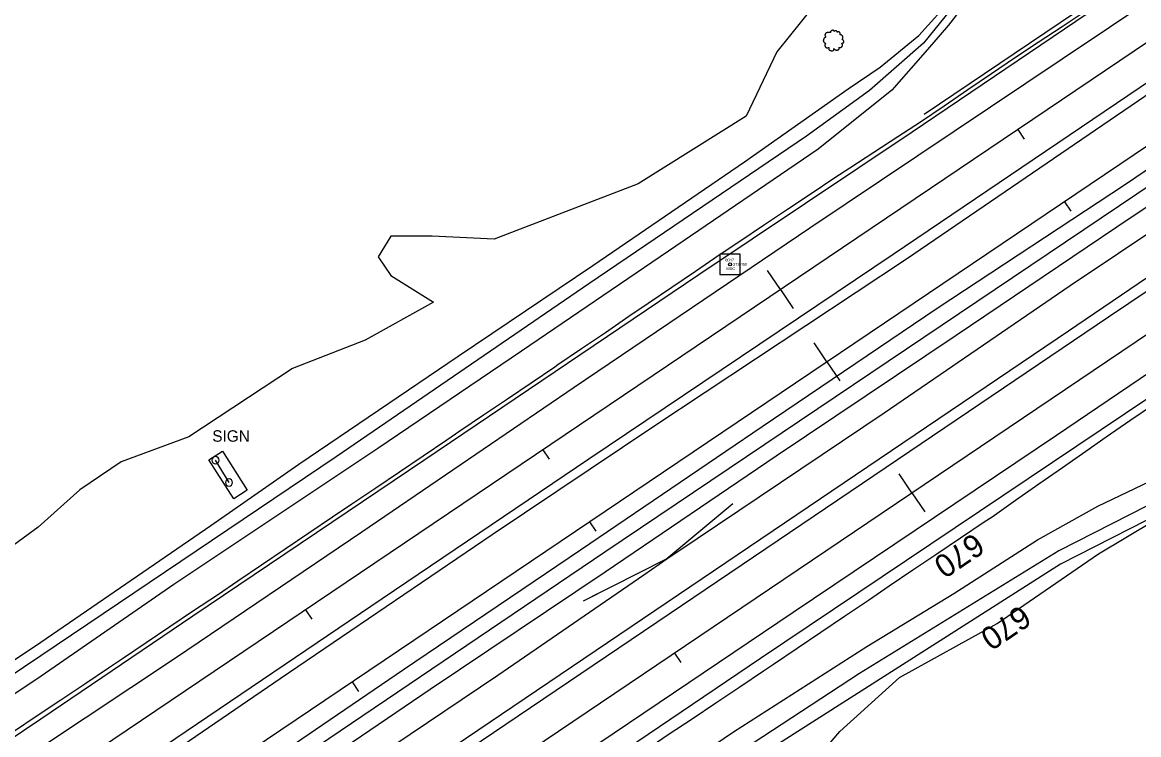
# Model space of a CAD drawing. Extents: x 1901471 to 1963503, y 756461 to 799997.
# Drawn here: x 1915593.4 to 1915983.2, y 764296.7 to 764545.6 of the extents above; entities that cross this region are included whole.
import ezdxf

# ---------------------------------------------------------------- set-up
doc = ezdxf.new("R2010")
doc.units = 0
for name, color, linetype in [('Default', 7, 'Continuous'), ('RD_DTM_BkLn1', 7, 'Continuous'), ('RD_EX_Bldg', 7, 'Continuous'), ('RD_EX_Conc', 7, 'Continuous'), ('RD_EX_DR_ErosCtrl', 7, 'Continuous'), ('RD_EX_Fence_Other', 7, 'Continuous'), ('RD_EX_GuardRail', 7, 'Continuous'), ('RD_EX_H2O', 7, 'Continuous'), ('RD_EX_Road', 7, 'Continuous'), ('RD_EX_Road_txCode', 7, 'Continuous'), ('RD_EX_VEG', 7, 'Continuous'), ('RD_HC_Cl', 7, 'Continuous'), ('RD_HC_Data_Tic', 7, 'Continuous'), ('RD_HC_Survey', 7, 'Continuous'), ('RD_HC_TX_Sta50', 7, 'Continuous'), ('RD_HC_txCode', 7, 'Continuous'), ('RD_SMD_Locator', 7, 'Continuous')]:
    doc.layers.add(name, color=color, linetype=linetype)

# ---------------------------------------------------------------- blocks, each defined once
blk = doc.blocks.new('T2')
at = {"layer": 'RD_EX_VEG'}
for points in [[(0.05, 7.21), (-0.25, 7.24), (-0.57, 7.14), (-0.82, 7.04), (-1.05, 6.96), (-1.27, 6.86), (-1.57, 6.69), (-1.8, 6.49), (-1.92, 6.24), (-1.97, 6.01), (-2.02, 5.74), (-2.02, 5.56), (-2.15, 5.54), (-2.3, 5.56), (-2.55, 5.64), (-2.8, 5.64), (-3.05, 5.64), (-3.4, 5.61), (-3.75, 5.61), (-4.02, 5.56), (-4.35, 5.51), (-4.72, 5.39), (-5.07, 5.26), (-5.37, 5.01), (-5.62, 4.54), (-5.75, 4.19), (-5.9, 3.94), (-5.75, 3.49), (-5.57, 3.14), (-5.55, 2.94), (-5.47, 2.52), (-5.37, 2.29), (-5.25, 2.09), (-5.32, 2.07), (-5.7, 2.02), (-6, 1.92), (-6.42, 1.69), (-6.64, 1.47), (-6.74, 1.14), (-6.77, 0.79), (-6.87, 0.59), (-6.94, 0.32), (-6.97, 0.24), (-7.02, -0.08), (-6.92, -0.53), (-6.89, -0.88), (-6.77, -1.11), (-6.62, -1.28), (-6.44, -1.53), (-6.05, -1.76), (-5.72, -1.86), (-5.52, -1.88), (-5.7, -2.38), (-5.75, -2.73), (-5.87, -3.13), (-5.87, -3.21), (-5.92, -3.68), (-5.77, -4.01), (-5.7, -4.38), (-5.52, -4.61), (-5.25, -4.91), (-4.92, -5.13), (-4.42, -5.26), (-4.02, -5.23), (-3.45, -5.06), (-3.2, -4.98), (-3.22, -5.16), (-3.2, -5.53), (-3.2, -5.96), (-3.05, -6.28), (-2.95, -6.56), (-2.8, -6.81), (-2.47, -7.03), (-2.07, -7.11), (-1.65, -7.26), (-1.2, -7.33), (-0.7, -7.36), (-0.1, -7.21), (0.18, -7.08), (0.28, -6.91), (0.48, -6.53), (0.43, -6.31), (0.45, -5.71), (0.55, -5.88), (0.73, -6.23), (1.23, -6.53), (1.63, -6.71), (2.1, -6.86), (2.4, -6.93), (2.88, -6.86), (3.25, -6.78), (3.63, -6.66), (3.93, -6.38), (4.1, -6.11), (4.15, -5.83), (4.23, -5.46), (4.28, -5.28)], [(4.28, -5.28), (4.2, -5.11), (4.15, -4.86), (4.23, -4.88), (4.4, -4.93), (4.68, -5.06), (4.9, -5.13), (5.23, -5.11), (5.5, -5.01), (5.95, -4.73), (6.22, -4.26), (6.5, -3.86), (6.57, -3.53), (6.52, -3.31), (6.5, -2.81), (6.3, -2.56), (6.25, -2.43), (6.15, -2.03), (6.22, -1.98), (6.5, -1.93), (6.87, -1.81), (7.15, -1.68), (7.37, -1.51), (7.45, -1.28), (7.42, -0.88), (7.47, -0.48), (7.4, -0.33), (7.3, -0.18), (7.22, 0.02), (7.07, 0.17), (6.97, 0.32), (6.87, 0.42), (6.75, 0.57), (6.57, 0.69), (6.42, 0.74), (6.37, 0.89), (6.52, 1.09), (6.57, 1.19), (6.6, 1.42), (6.82, 1.77), (6.87, 2.17), (6.82, 2.59), (6.77, 2.87), (6.62, 3.14), (6.42, 3.39), (6.3, 3.56), (6.12, 3.69), (5.8, 3.81), (5.55, 3.86), (5.2, 3.86), (5, 3.91), (5.03, 3.96), (5.03, 4.11), (5.03, 4.39), (4.95, 4.84), (4.8, 5.34), (4.8, 5.36), (4.7, 5.61), (4.48, 5.81), (4.3, 5.91), (4.1, 6.04), (3.85, 6.06), (3.55, 6.06), (3.28, 6.01), (3.08, 5.91), (2.9, 5.79), (2.83, 5.94), (2.73, 6.24), (2.68, 6.39), (2.53, 6.56), (2.3, 6.76), (1.85, 6.89), (1.23, 6.81), (0.93, 6.61), (0.78, 6.44), (0.73, 6.56), (0.53, 6.76), (0.43, 6.94), (0.25, 7.06), (0.1, 7.16), (0, 7.21)]]:
    blk.add_spline(points, degree=3, dxfattribs=at)
blk = doc.blocks.new('SIGNPOST')
at = {"layer": 'Default'}
for start, end in [(90, 270), (270, 90)]:
    blk.add_arc((0, 0), 0.127, start, end, dxfattribs=at)

msp = doc.modelspace()

# ---------------------------------------------------------------- linework, layer by layer
at = {"layer": 'RD_DTM_BkLn1'}
for points in [[(1915590.31, 764297.79), (1915598.62, 764303.35), (1915606.93, 764308.91), (1915615.23, 764314.47), (1915623.54, 764320.03), (1915628.37, 764323.26), (1915636.66, 764328.85), (1915644.95, 764334.44), (1915653.24, 764340.03), (1915661.53, 764345.61), (1915668.64, 764350.41), (1915676.92, 764356.01), (1915685.19, 764361.62), (1915693.47, 764367.23), (1915701.75, 764372.83), (1915708.51, 764377.41), (1915716.8, 764383), (1915725.09, 764388.59), (1915733.39, 764394.18), (1915741.68, 764399.76), (1915746.22, 764402.82), (1915754.49, 764408.43), (1915762.77, 764414.03), (1915771.04, 764419.64), (1915779.32, 764425.25), (1915780.44, 764426.01), (1915788.71, 764431.63), (1915796.98, 764437.25), (1915805.24, 764442.88), (1915811.94, 764447.44), (1915820.21, 764453.06), (1915828.48, 764458.68), (1915836.75, 764464.31), (1915843.9, 764469.17), (1915852.22, 764474.73), (1915860.53, 764480.28), (1915868.85, 764485.84), (1915877.16, 764491.4), (1915882.29, 764494.82), (1915890.68, 764500.26), (1915899.06, 764505.7), (1915906.97, 764510.83), (1915915.23, 764516.46), (1915923.49, 764522.09), (1915931.75, 764527.72), (1915939.79, 764533.19), (1915948.14, 764538.69), (1915956.49, 764544.19), (1915964.84, 764549.7)], [(1915811.5, 764291.58), (1915818.97, 764296.71), (1915827.27, 764302.28), (1915835.58, 764307.84), (1915843.88, 764313.41), (1915852.19, 764318.97), (1915855.7, 764321.32), (1915863.97, 764326.93), (1915872.25, 764332.54), (1915880.53, 764338.15), (1915888.81, 764343.75), (1915896.09, 764348.68), (1915904.38, 764354.27), (1915912.67, 764359.86), (1915920.96, 764365.44), (1915929.25, 764371.03), (1915931.99, 764372.87), (1915940.18, 764378.61), (1915948.38, 764384.34), (1915956.57, 764390.07), (1915964.76, 764395.8), (1915971.86, 764400.77), (1915980.1, 764406.42), (1915988.35, 764412.08)]]:
    msp.add_lwpolyline(points, dxfattribs=at)
at = {"layer": 'RD_EX_Bldg'}
msp.add_lwpolyline([(1915665.6, 764384.8), (1915660.88, 764392.59)], dxfattribs=at)
at = {"layer": 'RD_EX_Conc'}
msp.add_lwpolyline([(1915667.24, 764379.06), (1915658.55, 764392.68), (1915663.3, 764395.71), (1915671.99, 764382.08)], close=True, dxfattribs=at)
at = {"layer": 'RD_EX_DR_ErosCtrl'}
for points in [[(1915980.69, 764628.96), (1915946.91, 764583.63), (1915916.73, 764544.67), (1915909.43, 764536.12), (1915897.01, 764521.9), (1915871.29, 764501.25), (1915818.99, 764465.62), (1915767.66, 764430.75), (1915717.54, 764396.64), (1915646.38, 764349.19), (1915600.03, 764317.19), (1915543.38, 764279.27), (1915450.55, 764216.43), (1915363.64, 764158.21), (1915283.73, 764104.05), (1915199.21, 764046.19), (1915112.11, 763987.79), (1915024.45, 763928.27), (1914932.74, 763866.18)], [(1914945.29, 763885.74), (1915033.68, 763945.8), (1915126.13, 764008.64), (1915213.05, 764067.6), (1915303.29, 764128.41), (1915394.09, 764190.14), (1915479.9, 764248.73), (1915599.85, 764329), (1915659.24, 764369.73), (1915689.97, 764391.19), (1915745.65, 764428.95), (1915792.56, 764460.64), (1915845.58, 764496.84), (1915881.75, 764522.39), (1915892.98, 764529.96), (1915906.38, 764540.97), (1915918.47, 764554.37), (1915929.48, 764568.21), (1915951.71, 764597.36), (1915975.79, 764630.1)], [(1915576.12, 764217.67), (1915600.29, 764234), (1915662.85, 764276.06), (1915726.54, 764319.47), (1915788.29, 764361.3), (1915851.73, 764404.34), (1915912.87, 764445.69), (1915978.62, 764489.1), (1916039.03, 764530.08), (1916097.03, 764569), (1916153.93, 764606.84), (1916168.7, 764617.56), (1916176.33, 764608.96), (1916110.83, 764563.92), (1916044.84, 764520.15), (1915980.55, 764477.35), (1915919.41, 764436.12), (1915856.57, 764394.05), (1915796.88, 764353.43), (1915735.86, 764312.45), (1915672.66, 764269.53), (1915600.11, 764220.44), (1915443.62, 764114.7)], [(1914958.93, 763703.88), (1915040.11, 763759.4), (1915139.71, 763825.6), (1915192.23, 763861.39), (1915248.02, 763899.59), (1915351.54, 763966.71), (1915468.69, 764041.25), (1915527.64, 764081.4), (1915589.97, 764123.36), (1915754.25, 764238.29), (1915841.75, 764297.67), (1915888.32, 764327.51), (1915918.68, 764346.03), (1915947.91, 764364.79), (1915968.94, 764376.58), (1916015.51, 764398.77), (1916089.58, 764435.17), (1916134.58, 764454.55), (1916178.95, 764471.27)], [(1916181.45, 764461.27), (1916127.7, 764439.08), (1916022.07, 764390.02), (1915955.88, 764356.32), (1915854.88, 764291.89), (1915784.56, 764245.01), (1915659.87, 764161.1), (1915599.77, 764118.78), (1915560.33, 764091.37), (1915509.33, 764058.85), (1915438.17, 764014.44), (1915380.97, 763977.66), (1915253.58, 763893.49), (1915217.62, 763868.26), (1915174.25, 763838.89), (1915122.49, 763802.99), (1915074, 763769.48), (1915018.21, 763732.38), (1914963.07, 763694.62)]]:
    msp.add_lwpolyline(points, dxfattribs=at)
at = {"layer": 'RD_EX_Fence_Other'}
for points in [[(1914977.1, 763790), (1915017.33, 763817.5), (1915070.11, 763852.47), (1915114.03, 763882.55), (1915162.75, 763915.49), (1915201.5, 763941.51), (1915267.38, 763985.7), (1915334, 764030.82), (1915413.72, 764084.06), (1915492.34, 764137.3), (1915546.22, 764173.66), (1915598.45, 764209), (1915691.86, 764271.94), (1915759.45, 764317.53), (1915810.44, 764352.49), (1915818.43, 764358.15), (1915829.04, 764365.2), (1915894.31, 764409.21), (1915959.25, 764453.64), (1916026.02, 764498.4), (1916079.49, 764534.02), (1916134.63, 764571.64), (1916199.07, 764614.9)], [(1915841.44, 764377.34), (1915818.43, 764358.15), (1915789.25, 764343.38)], [(1915795.2, 764346.39), (1915789.25, 764343.38)], [(1915795.2, 764346.39), (1915789.25, 764343.38)]]:
    msp.add_lwpolyline(points, dxfattribs=at)
at = {"layer": 'RD_EX_GuardRail'}
msp.add_lwpolyline([(1915908.27, 764513.55), (1915987.16, 764566.86), (1915989.16, 764569.02), (1915992.64, 764571.35), (1915996.3, 764572.84), (1916021.21, 764589.28), (1916071.2, 764622.75), (1916076.02, 764626.24), (1916080.83, 764629.89), (1916086.15, 764633.05), (1916093.46, 764637.53), (1916105.25, 764645.34), (1916111.72, 764650.4), (1916115.54, 764653.56), (1916120.03, 764656.05), (1916124.18, 764658.54), (1916142.12, 764670.33), (1916167.69, 764687.27), (1916191.44, 764703.55)], dxfattribs=at)
at = {"layer": 'RD_EX_H2O'}
for points in [[(1915977.4, 764628.69), (1915943.82, 764582.64), (1915908.02, 764538.35), (1915889.19, 764521.75), (1915867.23, 764505.78), (1915791.2, 764454.21), (1915703, 764393.77), (1915599.85, 764324.2), (1915557.03, 764295.51), (1915469.56, 764236.18), (1915376.55, 764172.97), (1915287.42, 764112.91), (1915195.15, 764050.99), (1915104.36, 763989.26), (1915008.77, 763923.84), (1914924.8, 763867.47), (1914821.12, 763796.57), (1914784.02, 763769.81), (1914705.55, 763720.45), (1914641.2, 763674.13), (1914523.9, 763595.83), (1914449.47, 763547.6)], [(1914926.91, 763771.82), (1914947.95, 763785.75), (1915039.66, 763847.48), (1915129.35, 763908.29), (1915222.91, 763972.23), (1915314.44, 764034.7), (1915399.7, 764091.81), (1915495.47, 764156.31), (1915599.74, 764227.17), (1915796.78, 764360.53), (1916013.46, 764506.55), (1916139.86, 764591.45), (1916170.76, 764611.93)], [(1916176.7, 764464.63), (1916106.58, 764436.77), (1916016.71, 764392.29), (1915955.26, 764360.92), (1915885.69, 764318.02), (1915814.83, 764271.61), (1915733.63, 764216.71), (1915645.05, 764155.9), (1915594.01, 764120.3), (1915536.81, 764080.44), (1915451.69, 764026.77), (1915318.5, 763940.71), (1915231.93, 763883.36), (1915172.34, 763842.25), (1915132.27, 763815.11), (1915088.15, 763784.22), (1915015.28, 763735.02), (1914960.36, 763698.01), (1914910.43, 763664.64)]]:
    msp.add_lwpolyline(points, dxfattribs=at)
at = {"layer": 'RD_EX_Road'}
for points in [[(1916531.47, 764780.5), (1915851.13, 764323.29), (1915737.06, 764246.1), (1915599.37, 764150.96), (1915543.45, 764113.68), (1915458.75, 764056.01), (1915390.47, 764010.52), (1915257.79, 763920.47), (1915178.07, 763867.23), (1915092.44, 763808.64), (1915005.15, 763749.86), (1914923.77, 763695.33), (1914844.79, 763641.35)], [(1916263.29, 764739.29), (1916172.16, 764677.91), (1916117.99, 764641.46), (1916038.76, 764587.92), (1915956.49, 764532.73), (1915868.4, 764473.63), (1915786.13, 764418.06), (1915711.96, 764367.43), (1915646.9, 764323.39), (1915599.74, 764292.04), (1915501.38, 764225.42), (1915443.43, 764186.76), (1915376.26, 764141.82), (1915304.11, 764093.2), (1915236.93, 764047.8), (1915151.31, 763989.58), (1915093.36, 763950.36), (1915010.13, 763893.99), (1914936.13, 763844.07), (1914885.2, 763809.93), (1914816.55, 763763.52), (1914763.04, 763727.07), (1914680.36, 763671.06), (1914616.7, 763628.16)], [(1916190.54, 764700.38), (1916051.4, 764607), (1915904.14, 764507.17), (1915829.59, 764457.34), (1915733.63, 764392.48), (1915652.99, 764338.13), (1915599.92, 764302.1), (1915575.56, 764285.77), (1915496.58, 764232.34), (1915397.67, 764166.37), (1915301.34, 764101.13), (1915204.09, 764035.53), (1915108.31, 763970.48), (1915011.61, 763905.24), (1914919.71, 763843.15), (1914833.72, 763785.11), (1914734.43, 763718.03), (1914645.12, 763658.15), (1914556.17, 763597.34)], [(1914627.58, 763607.58), (1914704.35, 763659.35), (1914778.91, 763709.63), (1914863.43, 763767.12), (1914957.91, 763830.87), (1915026.74, 763877.29), (1915096.32, 763924.44), (1915171.61, 763975.28), (1915236.75, 764019.29), (1915308.17, 764067.55), (1915380.14, 764116.36), (1915452.85, 764165.17), (1915535.33, 764220.25), (1915599.19, 764263.53), (1915643.11, 764292.76), (1915719.05, 764344.27), (1915791.19, 764393.13), (1915897.51, 764464.64), (1916008.13, 764539.44), (1916110.9, 764608.93), (1916192.92, 764663.86)], [(1914698.82, 763651.23), (1914782.41, 763707.79), (1914855.12, 763756.78), (1914969.35, 763833.83), (1915113.85, 763932.74), (1915205.01, 763992.62), (1915294.7, 764053.8), (1915386.41, 764116.27), (1915543.82, 764222.01), (1915599.55, 764258.91), (1915683.43, 764316.36), (1915757.43, 764366.64), (1915814.27, 764404.75), (1915902.11, 764462.97), (1916002.5, 764531.53), (1916061, 764570), (1916154.74, 764633.39), (1916196.08, 764661.63)], [(1916297.72, 764632.72), (1916137.48, 764524.76), (1916045.34, 764462.87), (1915954.46, 764401.23), (1915862.58, 764339.34), (1915747.9, 764262), (1915682.34, 764217.32), (1915620.58, 764175.81), (1915600.11, 764161.75), (1915552.13, 764129.55), (1915489.94, 764087.57), (1915407.08, 764031.75), (1915322.19, 763974.45), (1915230.84, 763913.09), (1915167.73, 763870.37), (1915081, 763811.41), (1914989.84, 763749.68), (1914907.9, 763694.41), (1914835.56, 763645.41)], [(1914788.32, 763642.46), (1914879.11, 763703.82), (1914964.92, 763761.67), (1915047.97, 763817.86), (1915122.7, 763868.52), (1915210.18, 763927.67), (1915303, 763990.5), (1915373.49, 764037.84), (1915444.91, 764086.09), (1915506.92, 764127.8), (1915599.74, 764190.17), (1915722.84, 764273.65), (1915823.59, 764341.87), (1915894.98, 764390.22), (1915972.69, 764442.74), (1916021.29, 764475.4), (1916095.72, 764525.65), (1916149.38, 764561.59), (1916214.94, 764605.76)], [(1914758.98, 763627.05), (1914837.22, 763679.55), (1914925.43, 763739.62), (1915018.81, 763802.82), (1915104.8, 763860.68), (1915195.04, 763921.85), (1915289.9, 763986.16), (1915372.2, 764041.43), (1915455.24, 764097.26), (1915544.01, 764157.33), (1915599.55, 764194.69), (1915686.74, 764253.76), (1915797.69, 764328.92), (1915958.63, 764437.83), (1916059.57, 764506.43), (1916189.89, 764593.46)]]:
    msp.add_lwpolyline(points, dxfattribs=at)
at = {"layer": 'RD_EX_VEG'}
for points in [[(1915869.79, 764551.37), (1915856.85, 764535.34), (1915846.16, 764512.84), (1915808.47, 764489.21), (1915758.13, 764469.8), (1915736.47, 764470.93), (1915722.13, 764470.93), (1915717.63, 764463.62), (1915722.13, 764457.15), (1915737.03, 764447.87), (1915713.12, 764434.51), (1915687.81, 764424.66), (1915651.53, 764400.75), (1915627.9, 764392.04), (1915613.56, 764382.19), (1915598.91, 764369.16), (1915571.39, 764349.05)], [(1915580.68, 764082.42), (1915598.96, 764087.21), (1915627.43, 764103.48), (1915647.12, 764125.7), (1915685.93, 764148.76), (1915715.18, 764163.67), (1915724.18, 764165.78), (1915745.84, 764176.19), (1915772.28, 764195.88), (1915800.41, 764216.41), (1915824.6, 764243.41), (1915837.81, 764255.65), (1915857.5, 764272.8), (1915878.88, 764297.83), (1915899.69, 764316.68), (1915933.73, 764335.52), (1915969.16, 764359.85), (1916009.1, 764383.76), (1916052.42, 764404.86), (1916092.92, 764425.67), (1916120.77, 764437.06), (1916164.36, 764455.06), (1916187.71, 764462.94)]]:
    msp.add_lwpolyline(points, dxfattribs=at)
at = {"layer": 'RD_HC_Cl'}
for p, q in [((1916236.55, 764707.58), (1911792.37, 761708.94)), ((1916252.38, 764682.06), (1911757.65, 761649.35)), ((1916195.77, 764578.09), (1911854.45, 761647.95))]:
    msp.add_line(p, q, dxfattribs=at)
at = {"layer": 'RD_HC_Data_Tic'}
for p, q in [((1915940.98, 764508.14), (1915943.21, 764504.83)), ((1915957.26, 764482.93), (1915959.49, 764479.61)), ((1915858.08, 764452.21), (1915853.61, 764458.84)), ((1915858.08, 764452.21), (1915862.56, 764445.58)), ((1915874.36, 764427), (1915869.89, 764433.63)), ((1915874.36, 764427), (1915878.84, 764420.37)), ((1915775.19, 764396.28), (1915777.42, 764392.96)), ((1915904, 764381.16), (1915899.53, 764387.79)), ((1915904, 764381.16), (1915908.48, 764374.53)), ((1915791.47, 764371.07), (1915793.7, 764367.75)), ((1915692.29, 764340.35), (1915694.53, 764337.03)), ((1915821.12, 764325.22), (1915823.35, 764321.9)), ((1915708.57, 764315.13), (1915710.81, 764311.82))]:
    msp.add_line(p, q, dxfattribs=at)
at = {"layer": 'RD_HC_Survey'}
msp.add_lwpolyline([(1915844.07, 764464.57), (1915836.99, 764464.57), (1915836.99, 764457.5), (1915844.07, 764457.5)], close=True, dxfattribs=at)
msp.add_circle((1915840.53, 764461.04), 0.5, dxfattribs=at)
at = {"layer": 'RD_SMD_Locator'}
msp.add_circle((1915840.53, 764461.04), 0.001, dxfattribs=at)

# ---------------------------------------------------------------- block references
at = {"layer": 'RD_EX_Bldg', "xscale": 9.84251968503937, "yscale": 9.84251968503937}
for p in [(1915660.88, 764392.59), (1915665.6, 764384.8)]:
    msp.add_blockref('SIGNPOST', p, dxfattribs=at)
at = {"layer": 'RD_EX_VEG', "xscale": 0.4921259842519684, "yscale": 0.4921259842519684}
msp.add_blockref('T2', (1915876.54, 764539.28), dxfattribs=at)

# ---------------------------------------------------------------- texts
at = {"layer": 'RD_EX_Road'}
msp.add_text('SIGN', height=4, dxfattribs=at).set_placement((1915659.76, 764399.06))
at = {"layer": 'RD_EX_Road_txCode'}
msp.add_text('373.450', height=1, dxfattribs=at).set_placement((1915841.53, 764460.54))
at = {"layer": 'RD_HC_TX_Sta50'}
for rotation, p in [(214.0088, (1915925.73, 764367.57)), (214.0085, (1915942.01, 764342.36))]:
    msp.add_text('670', height=8, rotation=rotation, dxfattribs=at).set_placement(p)
at = {"layer": 'RD_HC_txCode'}
for s, p in [('8047', (1915838.86, 764462.04)), ('MSC', (1915839.22, 764459.04))]:
    msp.add_text(s, height=1, dxfattribs=at).set_placement(p)

doc.saveas('drawing.dxf')
